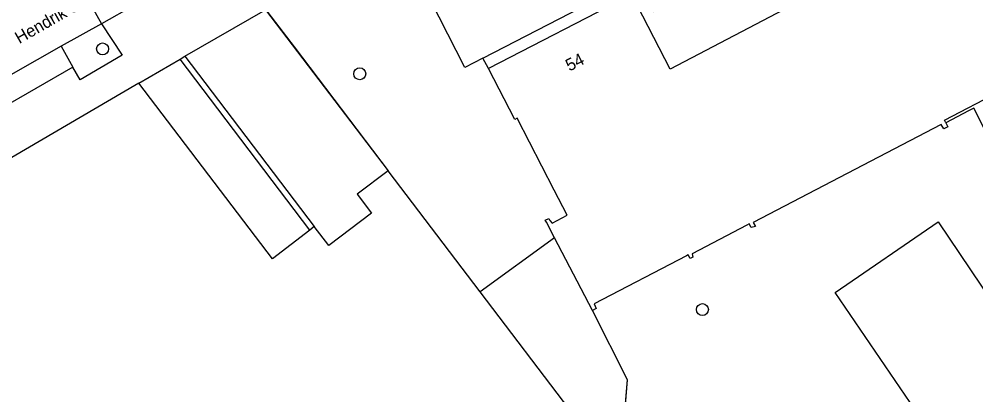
# Model space of a CAD drawing. Extents: x 160037 to 160839, y 385326 to 386441.
# Drawn here: x 160357.7 to 160436.3, y 386005.6 to 386036.4 of the extents above; entities that cross this region are included whole.
import ezdxf

# ---------------------------------------------------------------- set-up
doc = ezdxf.new("R2010")
doc.units = 0
for name, color, linetype in [('IMGEO_Boom', 7, 'Continuous'), ('IMGEO_Groenvoorziening', 7, 'Continuous'), ('IMGEO_Hek', 7, 'Continuous'), ('IMGEO_Muur', 7, 'Continuous'), ('IMGEO_Openbare_ruimte_label', 7, 'Continuous'), ('IMGEO_Pand', 7, 'Continuous'), ('IMGEO_Pand_nummerreeks', 7, 'Continuous'), ('IMGEO_Parkeervlak_open', 7, 'Continuous'), ('IMGEO_Rijbaan_lokaal_gesloten', 7, 'Continuous'), ('IMGEO_Rijbaan_lokaal_open', 7, 'Continuous'), ('IMGEO_Voetpad_gesloten', 7, 'Continuous'), ('IMGEO_Voetpad_open', 7, 'Continuous')]:
    doc.layers.add(name, color=color, linetype=linetype)

msp = doc.modelspace()

# ---------------------------------------------------------------- linework, layer by layer
at = {"layer": 'IMGEO_Boom'}
for centre in [(160364.553, 386033.966), (160385.665, 386031.922), (160413.8, 386012.586)]:
    msp.add_circle(centre, 0.489, dxfattribs=at)
at = {"layer": 'IMGEO_Groenvoorziening'}
msp.add_lwpolyline([(160407.063, 385999.441), (160407.227, 386001.951), (160407.646, 386006.836), (160404.764, 386012.501)], dxfattribs=at)
at = {"layer": 'IMGEO_Hek'}
for points in [[(160401.535, 386052.361), (160401.401, 386052.286), (160393.193, 386047.572), (160388.813, 386045.056), (160387.724, 386043.771), (160385.731, 386042.581), (160383.749, 386041.433), (160377.491, 386037.764), (160380.288, 386034.138), (160388.002, 386023.963)], [(160407.063, 385999.441), (160407.107, 386000), (160407.646, 386006.836), (160404.764, 386012.501)]]:
    msp.add_lwpolyline(points, dxfattribs=at)
at = {"layer": 'IMGEO_Muur'}
for points in [[(160370.92, 386033.128), (160371.309, 386033.359)], [(160371.309, 386033.359), (160381.937, 386019.389)], [(160381.561, 386019.099), (160370.92, 386033.128)]]:
    msp.add_lwpolyline(points, dxfattribs=at)
at = {"layer": 'IMGEO_Pand'}
for points in [[(160446.685, 386034.566), (160446.434, 386035.048), (160443.566, 386040.554), (160445.258, 386041.435), (160441.641, 386048.379), (160432.032, 386043.413), (160431.868, 386043.328), (160431.96, 386043.15), (160421.676, 386037.792), (160411.151, 386032.31), (160407.996, 386038.424), (160407.822, 386038.334), (160396.238, 386032.358)], [(160433.785, 386027.897), (160433.665, 386028.127), (160438.187, 386030.478), (160438.41, 386030.049), (160438.777, 386030.24), (160438.556, 386030.664), (160446.177, 386034.636), (160446.398, 386034.212), (160446.768, 386034.405), (160446.685, 386034.566)], [(160401.651, 386018.477), (160400.991, 386019.744), (160400.903, 386019.918), (160401.191, 386020.065), (160401.279, 386019.893), (160401.468, 386019.679), (160402.711, 386020.328), (160401.64, 386022.381), (160398.582, 386028.272), (160398.404, 386028.18), (160396.238, 386032.358)], [(160367.528, 386031.149), (160349.208, 386020.473), (160347.207, 386019.307), (160342.423, 386016.519), (160340.422, 386015.352), (160335.638, 386012.565), (160333.636, 386011.398), (160327.941, 386008.079)], [(160381.561, 386019.099), (160378.504, 386016.741), (160367.528, 386031.149)], [(160453.317, 386019.989), (160441.841, 386016.758), (160441.478, 386017.471), (160441.87, 386017.671), (160436.1, 386029.103), (160435.66, 386028.874), (160433.785, 386027.897)], [(160433.785, 386027.897), (160433.949, 386027.583), (160433.613, 386027.409), (160433.393, 386027.753), (160417.978, 386019.723), (160418.152, 386019.388), (160417.796, 386019.313), (160417.642, 386019.608), (160417.457, 386019.511), (160412.95, 386017.164), (160413.003, 386016.887), (160412.798, 386016.778), (160412.637, 386017.078), (160412.494, 386017.004), (160404.92, 386013.058), (160405.077, 386012.669), (160404.764, 386012.501)], [(160388.002, 386023.963), (160385.464, 386022.038), (160386.63, 386020.5), (160383.117, 386017.844), (160381.937, 386019.389)], [(160395.552, 386014.034), (160388.002, 386023.963)], [(160381.937, 386019.389), (160381.561, 386019.099)], [(160444.625, 386002.78), (160436.201, 385997.135), (160424.691, 386013.996), (160433.163, 386019.786), (160444.625, 386002.78)], [(160404.764, 386012.501), (160403.211, 386015.483), (160401.651, 386018.477)], [(160402.912, 386004.356), (160395.552, 386014.034)]]:
    msp.add_lwpolyline(points, dxfattribs=at)
at = {"layer": 'IMGEO_Parkeervlak_open'}
msp.add_lwpolyline([(160361.165, 386034.196), (160362.124, 386032.481)], dxfattribs=at)
at = {"layer": 'IMGEO_Rijbaan_lokaal_gesloten'}
msp.add_lwpolyline([(160367.528, 386031.149), (160370.92, 386033.128)], dxfattribs=at)
at = {"layer": 'IMGEO_Rijbaan_lokaal_open'}
for points in [[(160415.363, 386064.833), (160400.173, 386056.238), (160378.042, 386043.695), (160367.176, 386037.545), (160364.472, 386036.019)], [(160361.775, 386040.825), (160364.472, 386036.019)], [(160364.472, 386036.019), (160361.165, 386034.196)], [(160361.165, 386034.196), (160355.023, 386030.72)]]:
    msp.add_lwpolyline(points, dxfattribs=at)
at = {"layer": 'IMGEO_Voetpad_gesloten'}
for points in [[(160395.783, 386033.199), (160394.307, 386032.431), (160388.683, 386043.452)], [(160395.783, 386033.199), (160407.401, 386039.212), (160408.397, 386039.728), (160409.833, 386036.994)]]:
    msp.add_lwpolyline(points, dxfattribs=at)
at = {"layer": 'IMGEO_Voetpad_open'}
for points in [[(160371.309, 386033.359), (160377.931, 386037.165)], [(160377.931, 386037.165), (160388.002, 386023.963)], [(160364.472, 386036.019), (160366.154, 386033.444), (160362.715, 386031.422), (160362.124, 386032.481)], [(160362.124, 386032.481), (160356.008, 386028.971)], [(160396.238, 386032.358), (160395.783, 386033.199)], [(160401.651, 386018.477), (160395.552, 386014.034)]]:
    msp.add_lwpolyline(points, dxfattribs=at)

# ---------------------------------------------------------------- texts
at = {"layer": 'IMGEO_Openbare_ruimte_label'}
msp.add_text('Hendrik Staetslaan', height=1, rotation=29.74488, dxfattribs=at).set_placement((160357.717, 386034.351))
at = {"layer": 'IMGEO_Pand_nummerreeks'}
msp.add_text('54', height=1, rotation=27.28998, dxfattribs=at).set_placement((160402.887, 386032.098))

doc.saveas('drawing.dxf')
